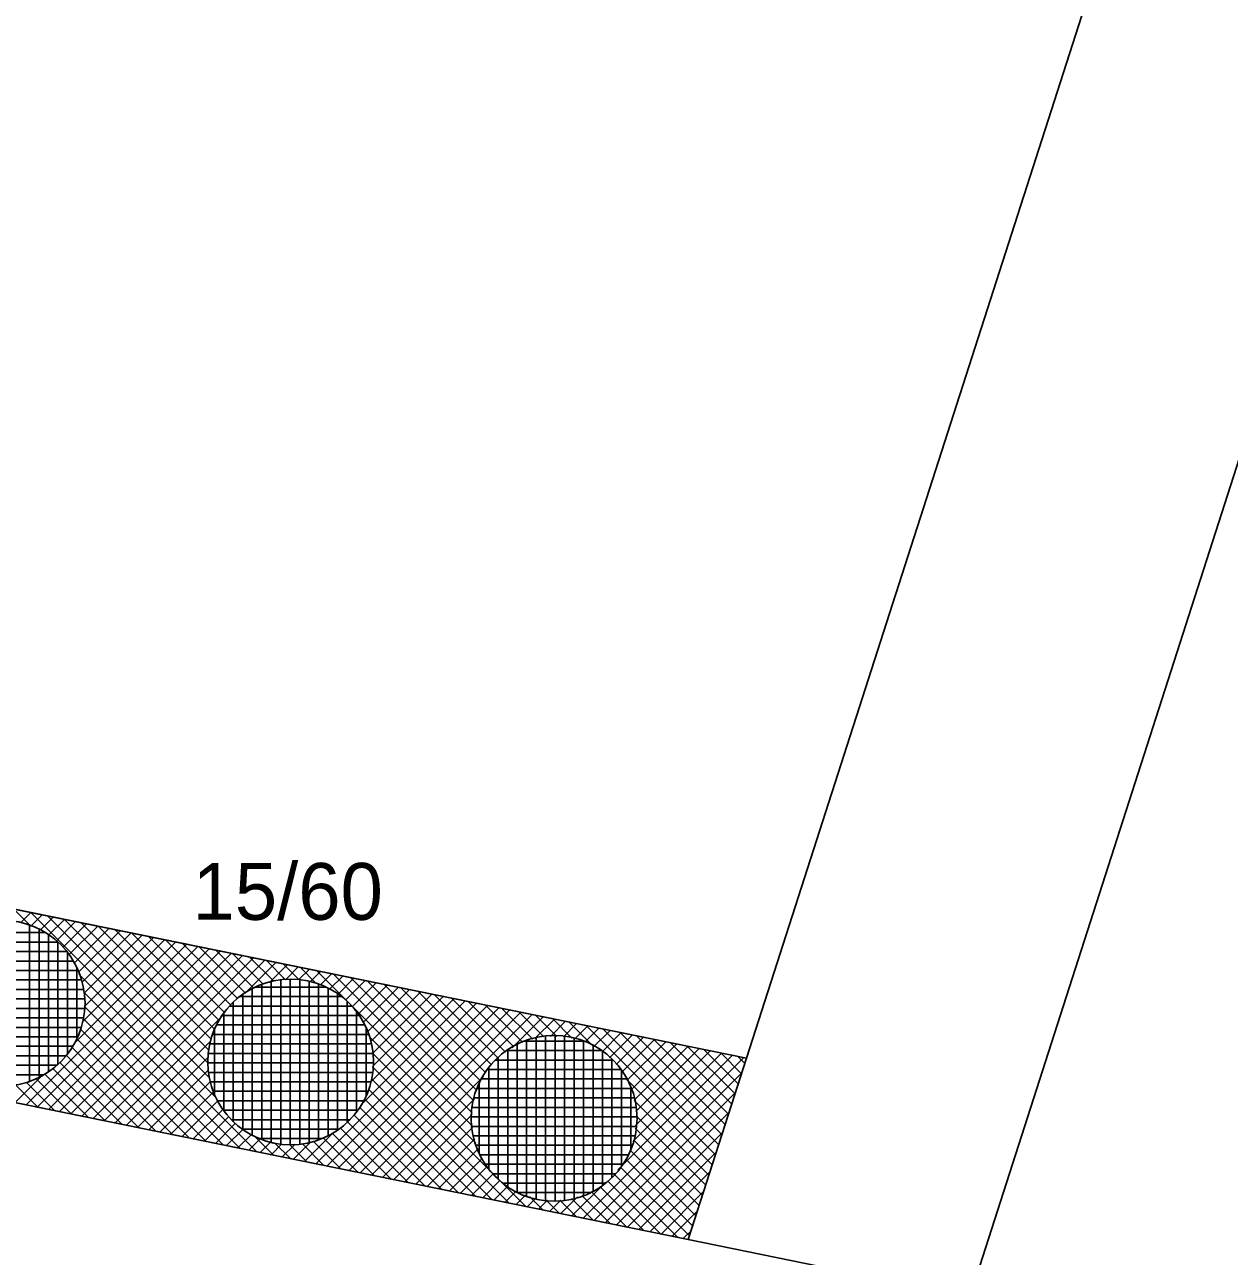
# Model space of a CAD drawing. Extents: x -566461 to -565198, y -1096301 to -1095707.
# Drawn here: x -565711.28 to -565685.86, y -1096140.58 to -1096114.58 of the extents above; entities that cross this region are included whole.
import ezdxf

# ---------------------------------------------------------------- set-up
doc = ezdxf.new("R2010")
doc.units = 0
for name, color, linetype in [('Vrstva 1', 7, 'Continuous'), ('Vrstva 40', 7, 'Continuous'), ('Vrstva 41', 7, 'Continuous'), ('Vrstva 42', 7, 'Continuous'), ('Vrstva 44', 7, 'Continuous')]:
    doc.layers.add(name, color=color, linetype=linetype)

msp = doc.modelspace()

# ---------------------------------------------------------------- linework, layer by layer
at = {"layer": 'Vrstva 1'}
for p, q in [((-565655.73, -1096030.58), (-565691.34, -1096141.44)), ((-565663.31, -1096034.56), (-565696.05, -1096136.4)), ((-565697.28, -1096140.23), (-565854, -1096108.33)), ((-565748.22, -1096125.78), (-565696.05, -1096136.4)), ((-565696.05, -1096136.4), (-565697.28, -1096140.23)), ((-565691.34, -1096141.44), (-565697.28, -1096140.23))]:
    msp.add_line(p, q, dxfattribs=at)
at = {"layer": 'Vrstva 41'}
for p, q in [((-565711.51, -1096133.253), (-565711.151, -1096133.612)), ((-565711.37, -1096133.545), (-565711.151, -1096133.326)), ((-565711.155, -1096133.325), (-565707.228, -1096137.252)), ((-565711.153, -1096133.611), (-565710.916, -1096133.374)), ((-565710.957, -1096133.699), (-565710.681, -1096133.422)), ((-565710.8, -1096133.398), (-565707.376, -1096136.822)), ((-565710.78, -1096133.804), (-565710.446, -1096133.47)), ((-565710.62, -1096133.927), (-565710.211, -1096133.518)), ((-565710.477, -1096134.066), (-565709.976, -1096133.566)), ((-565710.445, -1096133.47), (-565707.41, -1096136.505)), ((-565710.349, -1096134.222), (-565709.741, -1096133.613)), ((-565710.09, -1096133.542), (-565707.392, -1096136.24)), ((-565709.735, -1096133.615), (-565707.343, -1096136.006)), ((-565710.24, -1096134.395), (-565709.506, -1096133.661)), ((-565710.149, -1096134.587), (-565709.271, -1096133.709)), ((-565710.079, -1096134.8), (-565709.036, -1096133.757)), ((-565710.067, -1096135.637), (-565708.331, -1096133.9)), ((-565710.032, -1096135.036), (-565708.801, -1096133.805)), ((-565710.028, -1096135.315), (-565708.566, -1096133.853)), ((-565709.379, -1096133.687), (-565707.27, -1096135.796)), ((-565709.024, -1096133.759), (-565707.177, -1096135.607)), ((-565708.669, -1096133.831), (-565707.063, -1096135.437)), ((-565708.314, -1096133.904), (-565706.933, -1096135.284)), ((-565711.251, -1096137.386), (-565707.861, -1096133.996)), ((-565711.016, -1096137.434), (-565707.626, -1096134.044)), ((-565710.781, -1096137.482), (-565707.391, -1096134.092)), ((-565710.546, -1096137.53), (-565707.156, -1096134.14)), ((-565710.248, -1096136.101), (-565708.096, -1096133.948)), ((-565707.959, -1096133.976), (-565706.787, -1096135.147)), ((-565707.604, -1096134.048), (-565706.625, -1096135.027)), ((-565707.249, -1096134.121), (-565706.446, -1096134.924)), ((-565710.311, -1096137.578), (-565706.921, -1096134.187)), ((-565710.076, -1096137.625), (-565706.686, -1096134.235)), ((-565709.841, -1096137.673), (-565706.451, -1096134.283)), ((-565709.606, -1096137.721), (-565706.216, -1096134.331)), ((-565706.894, -1096134.193), (-565706.247, -1096134.839)), ((-565706.635, -1096135.034), (-565705.981, -1096134.379)), ((-565706.538, -1096134.265), (-565706.027, -1096134.776)), ((-565706.183, -1096134.337), (-565705.776, -1096134.745)), ((-565706.119, -1096134.8), (-565705.746, -1096134.427)), ((-565705.828, -1096134.41), (-565705.489, -1096134.749)), ((-565710.132, -1096134.631), (-565706.387, -1096138.376)), ((-565705.781, -1096134.745), (-565705.511, -1096134.474)), ((-565705.502, -1096134.748), (-565705.276, -1096134.522)), ((-565705.473, -1096134.482), (-565705.13, -1096134.825)), ((-565705.26, -1096134.79), (-565705.041, -1096134.57)), ((-565705.118, -1096134.554), (-565701.835, -1096137.838)), ((-565705.045, -1096134.857), (-565704.806, -1096134.618)), ((-565704.851, -1096134.946), (-565704.571, -1096134.666)), ((-565704.763, -1096134.627), (-565701.837, -1096137.552)), ((-565704.675, -1096135.053), (-565704.336, -1096134.714)), ((-565704.516, -1096135.177), (-565704.101, -1096134.761)), ((-565704.408, -1096134.699), (-565701.804, -1096137.303)), ((-565704.374, -1096135.318), (-565703.866, -1096134.809)), ((-565704.249, -1096135.475), (-565703.631, -1096134.857)), ((-565704.141, -1096135.65), (-565703.396, -1096134.905)), ((-565704.053, -1096134.771), (-565701.74, -1096137.084)), ((-565704.052, -1096135.844), (-565703.161, -1096134.953)), ((-565703.697, -1096134.843), (-565701.654, -1096136.887)), ((-565703.342, -1096134.916), (-565701.549, -1096136.709)), ((-565710.037, -1096135.009), (-565706.742, -1096138.304)), ((-565704.194, -1096137.401), (-565701.985, -1096135.192)), ((-565703.985, -1096136.908), (-565702.22, -1096135.144)), ((-565703.983, -1096136.058), (-565702.926, -1096135.001)), ((-565703.94, -1096136.58), (-565702.455, -1096135.096)), ((-565703.939, -1096136.297), (-565702.691, -1096135.048)), ((-565702.987, -1096134.988), (-565701.428, -1096136.547)), ((-565702.632, -1096135.06), (-565701.29, -1096136.402)), ((-565702.277, -1096135.133), (-565701.136, -1096136.274)), ((-565701.922, -1096135.205), (-565700.964, -1096136.162)), ((-565710.027, -1096135.303), (-565707.097, -1096138.232)), ((-565705.141, -1096138.63), (-565701.75, -1096135.24)), ((-565704.906, -1096138.678), (-565701.515, -1096135.288)), ((-565704.671, -1096138.726), (-565701.28, -1096135.335)), ((-565704.436, -1096138.773), (-565701.045, -1096135.383)), ((-565704.201, -1096138.821), (-565700.81, -1096135.431)), ((-565701.567, -1096135.277), (-565700.774, -1096136.07)), ((-565701.212, -1096135.349), (-565700.562, -1096135.999)), ((-565700.856, -1096135.422), (-565700.327, -1096135.952)), ((-565710.053, -1096135.558), (-565707.452, -1096138.159)), ((-565709.371, -1096137.769), (-565707.116, -1096135.515)), ((-565703.966, -1096138.869), (-565700.575, -1096135.479)), ((-565700.993, -1096136.18), (-565700.34, -1096135.527)), ((-565700.518, -1096135.987), (-565700.105, -1096135.575)), ((-565700.501, -1096135.494), (-565700.056, -1096135.94)), ((-565700.189, -1096135.941), (-565699.87, -1096135.622)), ((-565700.146, -1096135.566), (-565699.734, -1096135.978)), ((-565699.914, -1096135.948), (-565699.635, -1096135.67)), ((-565699.791, -1096135.639), (-565699.279, -1096136.151)), ((-565699.676, -1096135.994), (-565699.4, -1096135.718)), ((-565699.436, -1096135.711), (-565696.706, -1096138.441)), ((-565710.19, -1096135.987), (-565708.163, -1096138.015)), ((-565710.108, -1096135.786), (-565707.808, -1096138.087)), ((-565704.015, -1096135.94), (-565701.763, -1096138.192)), ((-565699.463, -1096136.064), (-565699.165, -1096135.766)), ((-565699.271, -1096136.155), (-565698.93, -1096135.814)), ((-565699.098, -1096136.264), (-565698.695, -1096135.862)), ((-565699.081, -1096135.783), (-565696.637, -1096138.227)), ((-565698.941, -1096136.391), (-565698.46, -1096135.909)), ((-565698.802, -1096136.534), (-565698.225, -1096135.957)), ((-565698.726, -1096135.855), (-565696.568, -1096138.013)), ((-565698.371, -1096135.928), (-565696.499, -1096137.799)), ((-565710.291, -1096136.169), (-565708.518, -1096137.943)), ((-565709.136, -1096137.817), (-565707.35, -1096136.031)), ((-565698.68, -1096136.694), (-565697.99, -1096136.005)), ((-565698.574, -1096136.871), (-565697.755, -1096136.053)), ((-565698.487, -1096137.067), (-565697.52, -1096136.101)), ((-565698.421, -1096137.284), (-565697.285, -1096136.149)), ((-565698.393, -1096137.822), (-565696.815, -1096136.244)), ((-565698.384, -1096137.53), (-565697.05, -1096136.196)), ((-565698.015, -1096136), (-565696.431, -1096137.585)), ((-565697.66, -1096136.072), (-565696.362, -1096137.371)), ((-565697.305, -1096136.145), (-565696.293, -1096137.157)), ((-565696.95, -1096136.217), (-565696.224, -1096136.943)), ((-565710.545, -1096136.482), (-565709.228, -1096137.798)), ((-565710.41, -1096136.334), (-565708.873, -1096137.87)), ((-565708.901, -1096137.865), (-565707.405, -1096136.369)), ((-565703.939, -1096136.299), (-565700.705, -1096139.533)), ((-565699.501, -1096139.778), (-565696.11, -1096136.388)), ((-565698.765, -1096138.76), (-565696.345, -1096136.34)), ((-565698.449, -1096138.161), (-565696.58, -1096136.292)), ((-565696.595, -1096136.289), (-565696.155, -1096136.728)), ((-565696.24, -1096136.361), (-565696.087, -1096136.514)), ((-565711.486, -1096137.338), (-565710.899, -1096136.752)), ((-565710.863, -1096136.729), (-565709.938, -1096137.653)), ((-565710.695, -1096136.614), (-565709.583, -1096137.726)), ((-565708.666, -1096137.912), (-565707.402, -1096136.648)), ((-565703.94, -1096136.581), (-565701.06, -1096139.461)), ((-565699.266, -1096139.826), (-565696.149, -1096136.71)), ((-565711.484, -1096136.956), (-565711.004, -1096137.437)), ((-565711.254, -1096136.904), (-565710.649, -1096137.509)), ((-565711.047, -1096136.828), (-565710.294, -1096137.581)), ((-565708.431, -1096137.96), (-565707.36, -1096136.89)), ((-565703.966, -1096136.837), (-565701.415, -1096139.388)), ((-565703.731, -1096138.917), (-565701.6, -1096136.787)), ((-565698.591, -1096136.839), (-565696.774, -1096138.655)), ((-565708.196, -1096138.008), (-565707.293, -1096137.105)), ((-565704.114, -1096137.256), (-565702.126, -1096139.244)), ((-565704.029, -1096137.057), (-565701.77, -1096139.316)), ((-565703.496, -1096138.965), (-565701.793, -1096137.262)), ((-565699.031, -1096139.874), (-565696.283, -1096137.126)), ((-565698.418, -1096137.294), (-565696.843, -1096138.869)), ((-565707.961, -1096138.056), (-565707.204, -1096137.299)), ((-565707.726, -1096138.104), (-565707.097, -1096137.475)), ((-565704.217, -1096137.435), (-565702.481, -1096139.171)), ((-565698.796, -1096139.922), (-565696.417, -1096137.543)), ((-565707.491, -1096138.152), (-565706.973, -1096137.634)), ((-565707.256, -1096138.199), (-565706.832, -1096137.776)), ((-565704.474, -1096137.743), (-565703.191, -1096139.027)), ((-565704.337, -1096137.597), (-565702.836, -1096139.099)), ((-565703.261, -1096139.013), (-565701.839, -1096137.591)), ((-565698.38, -1096137.616), (-565696.912, -1096139.083)), ((-565707.021, -1096138.247), (-565706.675, -1096137.901)), ((-565706.786, -1096138.295), (-565706.5, -1096138.009)), ((-565706.442, -1096138.038), (-565706.032, -1096138.449)), ((-565705.376, -1096138.582), (-565704.749, -1096137.956)), ((-565704.797, -1096137.987), (-565703.901, -1096138.882)), ((-565704.627, -1096137.873), (-565703.546, -1096138.955)), ((-565703.026, -1096139.06), (-565701.832, -1096137.866)), ((-565698.561, -1096139.969), (-565696.551, -1096137.96)), ((-565698.399, -1096137.88), (-565696.981, -1096139.298)), ((-565706.551, -1096138.343), (-565706.306, -1096138.098)), ((-565706.316, -1096138.391), (-565706.092, -1096138.167)), ((-565706.081, -1096138.439), (-565705.853, -1096138.211)), ((-565706.012, -1096138.186), (-565705.677, -1096138.521)), ((-565705.846, -1096138.486), (-565705.575, -1096138.216)), ((-565705.695, -1096138.22), (-565705.322, -1096138.593)), ((-565705.611, -1096138.534), (-565705.242, -1096138.165)), ((-565705.43, -1096138.202), (-565704.967, -1096138.665)), ((-565705.196, -1096138.153), (-565704.611, -1096138.738)), ((-565704.986, -1096138.08), (-565704.256, -1096138.81)), ((-565702.791, -1096139.108), (-565701.786, -1096138.104)), ((-565702.556, -1096139.156), (-565701.716, -1096138.317)), ((-565698.51, -1096138.334), (-565697.118, -1096139.726)), ((-565698.439, -1096138.122), (-565697.049, -1096139.512)), ((-565702.321, -1096139.204), (-565701.625, -1096138.509)), ((-565698.602, -1096138.524), (-565697.187, -1096139.94)), ((-565698.326, -1096140.017), (-565696.685, -1096138.376)), ((-565702.086, -1096139.252), (-565701.516, -1096138.682)), ((-565701.851, -1096139.3), (-565701.389, -1096138.839)), ((-565698.842, -1096138.85), (-565697.509, -1096140.183)), ((-565698.714, -1096138.696), (-565697.256, -1096140.154)), ((-565698.091, -1096140.065), (-565696.819, -1096138.793)), ((-565701.616, -1096139.347), (-565701.246, -1096138.978)), ((-565701.381, -1096139.395), (-565701.086, -1096139.1)), ((-565699.736, -1096139.73), (-565699.02, -1096139.015)), ((-565699.149, -1096139.109), (-565698.219, -1096140.039)), ((-565698.987, -1096138.988), (-565697.864, -1096140.111)), ((-565701.146, -1096139.443), (-565700.909, -1096139.206)), ((-565700.911, -1096139.491), (-565700.713, -1096139.293)), ((-565700.676, -1096139.539), (-565700.496, -1096139.359)), ((-565700.632, -1096139.323), (-565700.35, -1096139.605)), ((-565699.971, -1096139.682), (-565699.619, -1096139.331)), ((-565699.743, -1096139.364), (-565699.285, -1096139.822)), ((-565699.524, -1096139.3), (-565698.929, -1096139.894)), ((-565699.327, -1096139.214), (-565698.574, -1096139.967)), ((-565697.855, -1096140.113), (-565696.952, -1096139.21)), ((-565700.441, -1096139.587), (-565700.25, -1096139.396)), ((-565700.278, -1096139.395), (-565699.995, -1096139.677)), ((-565700.206, -1096139.635), (-565699.967, -1096139.396)), ((-565699.992, -1096139.397), (-565699.64, -1096139.75)), ((-565697.62, -1096140.161), (-565697.086, -1096139.626)), ((-565697.385, -1096140.209), (-565697.22, -1096140.043))]:
    msp.add_line(p, q, dxfattribs=at)
at = {"layer": 'Vrstva 42'}
msp.add_lwpolyline([(-565828.2, -1096027.12), (-565826.72, -1096023.51), (-565829.55, -1096025.32), (-565832.07, -1096026.09), (-565854, -1096108.33), (-565697.28, -1096140.23), (-565696.05, -1096136.4), (-565849.04, -1096105.26)], close=True, dxfattribs=at)
at = {"layer": 'Vrstva 44'}
for p, q in [((-565711.18, -1096136.89), (-565711.18, -1096133.591)), ((-565710.846, -1096133.75), (-565712.677, -1096133.75)), ((-565710.98, -1096136.806), (-565710.98, -1096133.675)), ((-565710.78, -1096136.687), (-565710.78, -1096133.791)), ((-565710.393, -1096134.15), (-565713.127, -1096134.15)), ((-565710.58, -1096133.95), (-565712.941, -1096133.95)), ((-565710.58, -1096136.532), (-565710.58, -1096133.95)), ((-565710.38, -1096136.314), (-565710.38, -1096134.167)), ((-565710.255, -1096134.35), (-565713.267, -1096134.35)), ((-565710.152, -1096134.55), (-565713.366, -1096134.55)), ((-565710.18, -1096135.991), (-565710.18, -1096134.492)), ((-565710.036, -1096134.95), (-565713.485, -1096134.95)), ((-565710.082, -1096134.75), (-565713.438, -1096134.75)), ((-565706.48, -1096138.031), (-565706.48, -1096134.93)), ((-565704.922, -1096134.9), (-565706.419, -1096134.9)), ((-565706.28, -1096138.119), (-565706.28, -1096134.841)), ((-565706.08, -1096138.181), (-565706.08, -1096134.781)), ((-565705.88, -1096138.217), (-565705.88, -1096134.745)), ((-565705.68, -1096138.229), (-565705.68, -1096134.731)), ((-565705.48, -1096138.218), (-565705.48, -1096134.74)), ((-565705.28, -1096138.184), (-565705.28, -1096134.775)), ((-565705.08, -1096138.127), (-565705.08, -1096134.835)), ((-565704.88, -1096138.04), (-565704.88, -1096134.92)), ((-565710.014, -1096135.15), (-565713.507, -1096135.15)), ((-565704.596, -1096135.1), (-565706.745, -1096135.1)), ((-565706.68, -1096137.907), (-565706.68, -1096135.053)), ((-565704.68, -1096137.921), (-565704.68, -1096135.038)), ((-565704.48, -1096137.762), (-565704.48, -1096135.199)), ((-565710.014, -1096135.35), (-565713.505, -1096135.35)), ((-565707.08, -1096137.514), (-565707.08, -1096135.444)), ((-565704.38, -1096135.3), (-565706.961, -1096135.3)), ((-565706.88, -1096137.744), (-565706.88, -1096135.217)), ((-565704.28, -1096137.542), (-565704.28, -1096135.42)), ((-565710.039, -1096135.55), (-565713.48, -1096135.55)), ((-565704.106, -1096135.7), (-565707.235, -1096135.7)), ((-565704.221, -1096135.5), (-565707.118, -1096135.5)), ((-565710.088, -1096135.75), (-565713.432, -1096135.75)), ((-565710.162, -1096135.95), (-565713.359, -1096135.95)), ((-565704.021, -1096135.9), (-565707.321, -1096135.9)), ((-565707.28, -1096137.162), (-565707.28, -1096135.799)), ((-565704.08, -1096137.208), (-565704.08, -1096135.752)), ((-565700.49, -1096139.378), (-565700.49, -1096135.964)), ((-565700.29, -1096139.409), (-565700.29, -1096135.931)), ((-565700.09, -1096139.418), (-565700.09, -1096135.92)), ((-565699.89, -1096139.404), (-565699.89, -1096135.935)), ((-565699.69, -1096139.368), (-565699.69, -1096135.973)), ((-565710.265, -1096136.15), (-565713.253, -1096136.15)), ((-565703.962, -1096136.1), (-565707.377, -1096136.1)), ((-565699.104, -1096136.24), (-565701.115, -1096136.24)), ((-565701.09, -1096139.118), (-565701.09, -1096136.222)), ((-565700.89, -1096139.235), (-565700.89, -1096136.104)), ((-565699.478, -1096136.04), (-565700.746, -1096136.04)), ((-565700.69, -1096139.319), (-565700.69, -1096136.021)), ((-565699.49, -1096139.306), (-565699.49, -1096136.035)), ((-565699.29, -1096139.214), (-565699.29, -1096136.124)), ((-565699.09, -1096139.09), (-565699.09, -1096136.25)), ((-565710.41, -1096136.35), (-565713.111, -1096136.35)), ((-565703.922, -1096136.5), (-565707.418, -1096136.5)), ((-565703.931, -1096136.3), (-565707.409, -1096136.3)), ((-565698.866, -1096136.44), (-565701.352, -1096136.44)), ((-565701.29, -1096138.96), (-565701.29, -1096136.379)), ((-565698.89, -1096138.922), (-565698.89, -1096136.416)), ((-565710.601, -1096136.55), (-565712.917, -1096136.55)), ((-565710.878, -1096136.75), (-565712.641, -1096136.75)), ((-565703.936, -1096136.7), (-565707.405, -1096136.7)), ((-565698.697, -1096136.64), (-565701.525, -1096136.64)), ((-565701.49, -1096138.743), (-565701.49, -1096136.597)), ((-565698.69, -1096138.691), (-565698.69, -1096136.65)), ((-565703.972, -1096136.9), (-565707.368, -1096136.9)), ((-565701.69, -1096138.419), (-565701.69, -1096136.919)), ((-565698.57, -1096136.84), (-565701.648, -1096136.84)), ((-565698.49, -1096138.327), (-565698.49, -1096137.012)), ((-565704.034, -1096137.1), (-565707.305, -1096137.1)), ((-565698.415, -1096137.24), (-565701.806, -1096137.24)), ((-565698.479, -1096137.04), (-565701.741, -1096137.04)), ((-565704.126, -1096137.3), (-565707.214, -1096137.3)), ((-565704.25, -1096137.5), (-565707.091, -1096137.5)), ((-565698.376, -1096137.44), (-565701.844, -1096137.44)), ((-565704.418, -1096137.7), (-565706.922, -1096137.7)), ((-565698.361, -1096137.64), (-565701.858, -1096137.64)), ((-565704.649, -1096137.9), (-565706.689, -1096137.9)), ((-565698.37, -1096137.84), (-565701.85, -1096137.84)), ((-565698.402, -1096138.04), (-565701.819, -1096138.04)), ((-565705.013, -1096138.1), (-565706.331, -1096138.1)), ((-565698.457, -1096138.24), (-565701.764, -1096138.24)), ((-565698.539, -1096138.44), (-565701.679, -1096138.44)), ((-565698.656, -1096138.64), (-565701.565, -1096138.64)), ((-565698.809, -1096138.84), (-565701.409, -1096138.84)), ((-565699.024, -1096139.04), (-565701.199, -1096139.04)), ((-565699.338, -1096139.24), (-565700.88, -1096139.24))]:
    msp.add_line(p, q, dxfattribs=at)
for centre in [(-565711.76, -1096135.24), (-565705.67, -1096136.48), (-565700.11, -1096137.67)]:
    msp.add_circle(centre, 1.75, dxfattribs=at)

# ---------------------------------------------------------------- texts
at = {"layer": 'Vrstva 40'}
msp.add_text('15/60', height=1.2, dxfattribs=at).set_placement((-565707.74, -1096133.48))

doc.saveas('drawing.dxf')
